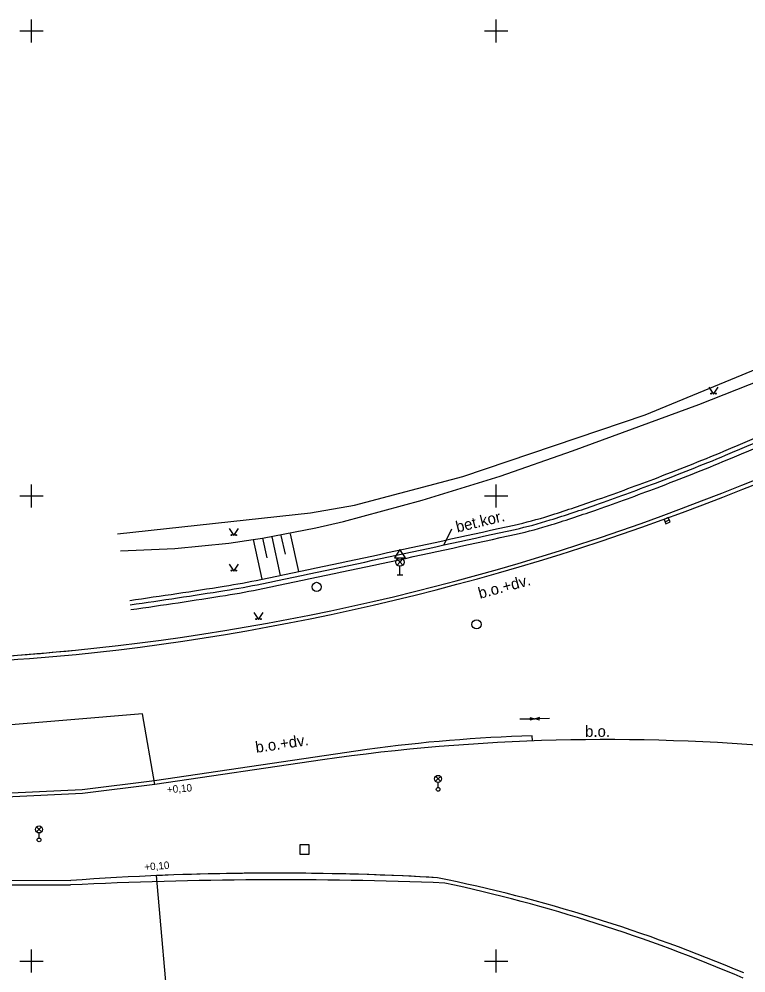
# Model space of a CAD drawing. Extents: x -599151 to -598424, y -1163476 to -1161924.
# Drawn here: x -598975.7 to -598936.6, y -1163175.6 to -1163124.4 of the extents above; entities that cross this region are included whole.
import ezdxf

# ---------------------------------------------------------------- set-up
doc = ezdxf.new("R2010")
doc.units = 0
for name, color, linetype in [('Vrstva 10', 7, 'Continuous'), ('Vrstva 14', 7, 'Continuous'), ('Vrstva 23', 7, 'Continuous'), ('Vrstva 25', 7, 'Continuous'), ('Vrstva 29', 7, 'Continuous'), ('Vrstva 41', 7, 'Continuous'), ('Vrstva 44', 7, 'Continuous'), ('Vrstva 49', 7, 'Continuous'), ('Vrstva 50', 7, 'Continuous'), ('Vrstva 62', 7, 'Continuous'), ('Vrstva 63', 7, 'Continuous'), ('Vrstva 7', 7, 'Continuous')]:
    doc.layers.add(name, color=color, linetype=linetype)

msp = doc.modelspace()

# ---------------------------------------------------------------- linework, layer by layer
at = {"layer": 'Vrstva 10'}
msp.add_lwpolyline([(-598970.37, -1163152.041), (-598959.99, -1163150.901), (-598957.62, -1163150.501), (-598951.79, -1163148.951), (-598942, -1163145.641), (-598933.08, -1163141.961), (-598925.88, -1163138.781), (-598922.03, -1163136.681), (-598910.98, -1163129.171), (-598909.98, -1163128.361), (-598909.39, -1163124.361)], dxfattribs=at)
at = {"layer": 'Vrstva 14'}
for points in [[(-598938.56, -1163144.144), (-598938.31, -1163144.519), (-598938.06, -1163144.144)], [(-598964.368, -1163151.754), (-598964.118, -1163152.129), (-598963.868, -1163151.754)], [(-598964.368, -1163153.662), (-598964.118, -1163154.037), (-598963.868, -1163153.662)], [(-598963.032, -1163156.269), (-598962.782, -1163156.644), (-598962.532, -1163156.269)]]:
    msp.add_lwpolyline(points, dxfattribs=at)
for centre in [(-598938.435, -1163144.494), (-598938.185, -1163144.494), (-598964.243, -1163152.104), (-598963.993, -1163152.104), (-598964.243, -1163154.012), (-598963.993, -1163154.012), (-598962.907, -1163156.619), (-598962.657, -1163156.619)]:
    msp.add_circle(centre, 0.025, dxfattribs=at)
at = {"layer": 'Vrstva 23'}
for p, q in [((-598960.06, -1163168.76), (-598960.56, -1163168.76)), ((-598960.56, -1163168.76), (-598960.56, -1163169.26)), ((-598960.06, -1163169.26), (-598960.06, -1163168.76)), ((-598960.56, -1163169.26), (-598960.06, -1163169.26))]:
    msp.add_line(p, q, dxfattribs=at)
at = {"layer": 'Vrstva 25'}
msp.add_line((-598940.924, -1163151.381), (-598940.696, -1163151.279), dxfattribs=at)
msp.add_lwpolyline([(-598940.873, -1163151.495), (-598940.645, -1163151.393), (-598940.747, -1163151.165), (-598940.975, -1163151.267)], close=True, dxfattribs=at)
for centre in [(-598959.66, -1163154.891), (-598951.06, -1163156.9)]:
    msp.add_circle(centre, 0.25, dxfattribs=at)
at = {"layer": 'Vrstva 29'}
for p, q in [((-598953.262, -1163165.339), (-598952.998, -1163165.075)), ((-598952.994, -1163165.338), (-598953.258, -1163165.073)), ((-598953.13, -1163165.67), (-598953.13, -1163165.395)), ((-598974.722, -1163168.059), (-598974.458, -1163167.795)), ((-598974.454, -1163168.058), (-598974.718, -1163167.793)), ((-598974.59, -1163168.39), (-598974.59, -1163168.115))]:
    msp.add_line(p, q, dxfattribs=at)
for centre, radius in [((-598953.13, -1163165.208), 0.188), ((-598953.13, -1163165.77), 0.1), ((-598974.59, -1163167.927), 0.188), ((-598974.59, -1163168.49), 0.1)]:
    msp.add_circle(centre, radius, dxfattribs=at)
at = {"layer": 'Vrstva 41'}
for points in [[(-598962.571, -1163152.267), (-598959.703, -1163151.72), (-598958.21, -1163151.37), (-598953.982, -1163150.231), (-598949.798, -1163148.938), (-598945.902, -1163147.581), (-598939.112, -1163145.084), (-598932.379, -1163142.438), (-598929.387, -1163141.206), (-598926.789, -1163140.066), (-598924.26, -1163138.782), (-598921.599, -1163137.228), (-598919.042, -1163135.568)], [(-598963.066, -1163152.345), (-598962.571, -1163152.267)], [(-598962.571, -1163152.267), (-598962.343, -1163153.318)], [(-598962.074, -1163152.201), (-598961.623, -1163154.269)], [(-598961.58, -1163152.121), (-598961.359, -1163153.133)], [(-598961.088, -1163152.033), (-598960.644, -1163154.064)], [(-598970.21, -1163152.95), (-598967.293, -1163152.82), (-598964.388, -1163152.531), (-598963.066, -1163152.345)], [(-598963.066, -1163152.345), (-598962.603, -1163154.474)]]:
    msp.add_lwpolyline(points, dxfattribs=at)
for centre, radius, start, end in [((-599065.283, -1162841.183), 332.12, 292.5952, 293.74558), ((-598984.869, -1163034.411), 122.828, 290.70357, 292.5952), ((-598991.012, -1163018.157), 140.204, 289.31263, 290.70357), ((-598971.352, -1163074.257), 80.76, 287.47996, 289.31263), ((-598953.834, -1163129.885), 22.439, 282.4623, 287.48), ((-599192.362, -1162050.596), 1127.77, 281.754586, 282.462339), ((-598971.425, -1163112.366), 43.258, 279.0808, 281.7546), ((-599008.874, -1162878.063), 280.534, 278.03078, 279.08079)]:
    msp.add_arc(centre, radius, start, end, dxfattribs=at)
at = {"layer": 'Vrstva 44'}
for p, q in [((-598955.03, -1163153.38), (-598955.33, -1163153.724)), ((-598955.33, -1163153.38), (-598955.03, -1163153.724)), ((-598955.18, -1163154.23), (-598955.18, -1163153.78)), ((-598955.33, -1163154.23), (-598955.03, -1163154.23))]:
    msp.add_line(p, q, dxfattribs=at)
msp.add_lwpolyline([(-598955.48, -1163153.324), (-598954.88, -1163153.324), (-598955.18, -1163152.874), (-598955.48, -1163153.324)], dxfattribs=at)
msp.add_circle((-598955.18, -1163153.552), 0.228, dxfattribs=at)
at = {"layer": 'Vrstva 49'}
for p, q in [((-598952.402, -1163151.79), (-598952.836, -1163152.655)), ((-598948.726, -1163161.988), (-598947.934, -1163161.977)), ((-598948.204, -1163161.909), (-598947.934, -1163161.977)), ((-598947.934, -1163161.977), (-598948.203, -1163162.053)), ((-598947.934, -1163161.977), (-598947.665, -1163161.899)), ((-598947.142, -1163161.966), (-598947.934, -1163161.977)), ((-598947.663, -1163162.045), (-598947.934, -1163161.977))]:
    msp.add_line(p, q, dxfattribs=at)
at = {"layer": 'Vrstva 62'}
for p, q in [((-598975, -1163125.625), (-598975, -1163124.375)), ((-598950, -1163125.625), (-598950, -1163124.375)), ((-598975.625, -1163125), (-598974.375, -1163125)), ((-598950.625, -1163125), (-598949.375, -1163125)), ((-598975, -1163150.625), (-598975, -1163149.375)), ((-598950, -1163150.625), (-598950, -1163149.375)), ((-598975.625, -1163150), (-598974.375, -1163150)), ((-598950.625, -1163150), (-598949.375, -1163150)), ((-598975, -1163175.625), (-598975, -1163174.375)), ((-598950, -1163175.625), (-598950, -1163174.375)), ((-598975.625, -1163175), (-598974.375, -1163175)), ((-598950.625, -1163175), (-598949.375, -1163175))]:
    msp.add_line(p, q, dxfattribs=at)
at = {"layer": 'Vrstva 63'}
for points in [[(-598959.35, -1163164.18), (-598968.36, -1163165.51), (-598969.03, -1163161.72), (-598980.83, -1163162.69), (-598980.94, -1163158.92)], [(-598967.543, -1163178.748), (-598968.28, -1163170.41)]]:
    msp.add_lwpolyline(points, dxfattribs=at)
for centre, radius, start, end in [((-598977.73, -1163042.484), 114.492, 290.94636, 304.36727), ((-598985.391, -1163030.077), 128.846, 275.68371, 292.15538), ((-598993.975, -1162931.856), 227.438, 273.28565, 275.38521), ((-598944.061, -1163271.589), 108.492, 84.76397, 98.10136), ((-598961.845, -1163325.084), 154.808, 86.78397, 92.38238), ((-598970.678, -1163255.923), 87.181, 67.05436, 78.40803)]:
    msp.add_arc(centre, radius, start, end, dxfattribs=at)
at = {"layer": 'Vrstva 7'}
for p, q in [((-598948.06, -1163163.171), (-598948.07, -1163162.89)), ((-598992.19, -1163170.89), (-598972.9, -1163170.91))]:
    msp.add_line(p, q, dxfattribs=at)
for points in [[(-598956.938, -1163163.622), (-598968.387, -1163165.312), (-598972.267, -1163165.791), (-598992.15, -1163166.72)], [(-598959.35, -1163164.18), (-598968.36, -1163165.51), (-598972.25, -1163165.99), (-598992.14, -1163166.94)], [(-598992.24, -1163170.64), (-598972.88, -1163170.67)]]:
    msp.add_lwpolyline(points, dxfattribs=at)
for centre, radius, start, end in [((-598977.73, -1163042.484), 114.492, 290.94636, 304.36727), ((-598979.155, -1163039.68), 117.847, 291.09498, 304.17356), ((-599065.283, -1162841.183), 331.885, 292.5952, 293.74558), ((-599065.283, -1162841.183), 332.385, 292.5952, 293.74558), ((-598984.869, -1163034.411), 122.593, 290.70357, 292.5952), ((-598984.869, -1163034.411), 123.093, 290.70357, 292.5952), ((-598991.012, -1163018.157), 139.969, 289.31263, 290.70357), ((-598985.391, -1163030.077), 128.846, 275.68371, 292.15538), ((-598986.535, -1163025.69), 133.569, 275.98838, 291.88853), ((-598991.012, -1163018.157), 140.469, 289.31263, 290.70357), ((-598971.352, -1163074.257), 80.524, 287.47996, 289.31263), ((-598971.352, -1163074.257), 81.024, 287.47996, 289.31263), ((-598953.834, -1163129.885), 22.203, 282.4623, 287.48), ((-599192.362, -1162050.596), 1127.535, 281.754586, 282.462339), ((-598953.834, -1163129.885), 22.703, 282.4623, 287.48), ((-599192.362, -1162050.596), 1128.035, 281.754586, 282.462339), ((-599008.874, -1162878.063), 280.298, 278.03078, 279.08079), ((-598971.425, -1163112.366), 43.022, 279.0808, 281.7546), ((-599008.874, -1162878.063), 280.798, 278.03078, 279.08079), ((-598971.425, -1163112.366), 43.522, 279.0808, 281.7546), ((-598993.975, -1162931.856), 227.438, 270.33389, 275.38521), ((-598997.073, -1162866.606), 292.948, 270.87283, 274.792), ((-598945.242, -1163251.285), 88.44, 91.83257, 97.59946), ((-598944.061, -1163271.589), 108.492, 84.76397, 98.10136), ((-598961.643, -1163401.209), 230.574, 87.79399, 92.79851), ((-598961.845, -1163325.084), 154.808, 86.78397, 94.08765), ((-598970.678, -1163255.923), 87.181, 67.05436, 78.40803), ((-598971.154, -1163256.167), 87.319, 66.78182, 77.84413)]:
    msp.add_arc(centre, radius, start, end, dxfattribs=at)

# ---------------------------------------------------------------- texts
at = {"layer": 'Vrstva 49'}
for s, rotation, p in [('bet.kor.', 13.6578, (-598952.095, -1163151.967)), ('b.o.+dv.', 15.1894, (-598950.878, -1163155.53)), ('b.o.+dv.', 8.397, (-598962.908, -1163163.811))]:
    msp.add_text(s, height=0.6, rotation=rotation, dxfattribs=at).set_placement(p)
msp.add_text('b.o.', height=0.6, dxfattribs=at).set_placement((-598945.223, -1163162.948))
at = {"layer": 'Vrstva 50'}
for p in [(-598967.697, -1163165.985), (-598968.915, -1163170.146)]:
    msp.add_text('+0,10', height=0.4, rotation=4.6297, dxfattribs=at).set_placement(p)

doc.saveas('drawing.dxf')
